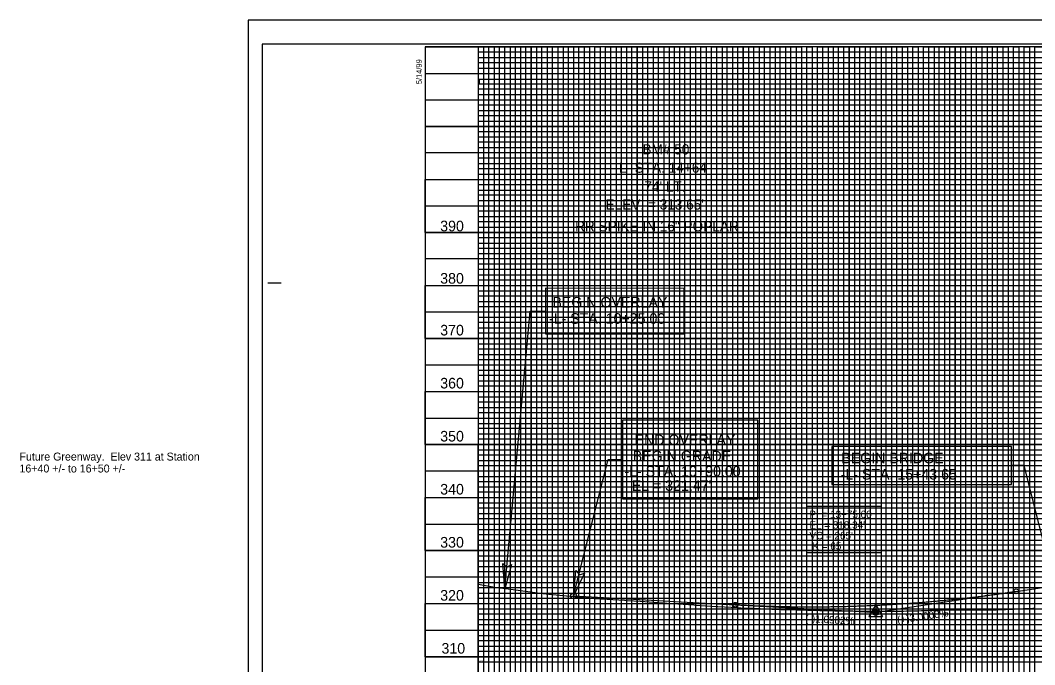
# Model space of a CAD drawing. Extents: x 574125 to 576234, y -56630 to -55530.
# Drawn here: x 574125 to 575082, y -56137 to -55530 of the extents above; entities that cross this region are included whole.
import ezdxf

# ---------------------------------------------------------------- set-up
doc = ezdxf.new("R2010")
doc.units = 0
for name, color, linetype in [('Default', 7, 'Continuous'), ('Exist Profile Cell', 7, 'Continuous'), ('Exist Vertical Profile Ground Line', 7, 'Continuous'), ('Exist Vertical Profile Vertical Axis Label', 7, 'Continuous'), ('Prop Grid Mask', 7, 'Continuous'), ('Prop PFL VPI Symbol CELL', 7, 'Continuous'), ('Prop Roadway Profile Bench Mark Info Text', 7, 'Continuous'), ('Prop Vertical Profile Curve Label', 7, 'Continuous'), ('Prop Vertical Profile Grade', 7, 'Continuous'), ('Prop Vertical Profile Grade Label', 7, 'Continuous'), ('Prop VPI Label', 7, 'Continuous'), ('Sheet DOT Grid CELL', 7, 'Continuous'), ('Sheet Plot Border Inside CELL', 7, 'Continuous'), ('Sheet Plot Border Outside CELL', 7, 'Continuous'), ('Sheet Profile CELL', 7, 'Continuous'), ('Sheet Profile Grid Major CELL', 7, 'Continuous'), ('Sheet Profile Grid Middle CELL', 7, 'Continuous'), ('Sheet Profile Grid Minor CELL', 7, 'Continuous'), ('Typical Terminator CELL', 7, 'Continuous')]:
    doc.layers.add(name, color=color, linetype=linetype)

msp = doc.modelspace()

# ---------------------------------------------------------------- linework, layer by layer
at = {"layer": 'Exist Profile Cell'}
msp.add_line((574556.81, -56179.85), (574556.81, -55929.85), dxfattribs=at)
at = {"layer": 'Exist Vertical Profile Ground Line'}
for points in [[(574556.81, -56061.37), (574572.39, -56064.2), (574584.89, -56065.93), (574585.5, -56066.03), (574614.78, -56070.08), (574615.19, -56070.12), (574626.34, -56071.21), (574627.11, -56071.28), (574656.54, -56074.14), (574667.14, -56074.83), (574667.54, -56074.87), (574694.84, -56076.65), (574697.37, -56076.82), (574709.71, -56077.66), (574739.43, -56079.69), (574740.03, -56079.73), (574760.22, -56081.05), (574761.44, -56081.13), (574781.02, -56082.41), (574782.8, -56082.51), (574801.58, -56083.57), (574804.41, -56083.71), (574814.2, -56084.14), (574817.02, -56084.26), (574819.84, -56084.38), (574822.04, -56084.48), (574822.66, -56084.5), (574825.48, -56084.6), (574826.57, -56084.64), (574828.31, -56084.7), (574831.13, -56084.8), (574833.95, -56084.9), (574836.77, -56085), (574839.59, -56085.1), (574842.57, -56085.21), (574845.23, -56085.27), (574848.12, -56085.35), (574850.87, -56085.43), (574853.69, -56085.51), (574856.51, -56085.59), (574859.33, -56085.67), (574862.15, -56085.75), (574863.21, -56085.78), (574864.98, -56085.82), (574867.8, -56085.89), (574869.54, -56085.93), (574870.62, -56085.96), (574873.44, -56086.02), (574876.26, -56086.09), (574879.08, -56086.16), (574881.9, -56086.23), (574885.01, -56086.3), (574887.54, -56086.36), (574890.36, -56086.42), (574891.83, -56086.45), (574893.18, -56086.47), (574896, -56086.52), (574898.82, -56086.57), (574901.65, -56086.62), (574904.47, -56086.67), (574906.83, -56086.71), (574907.29, -56086.72), (574910.11, -56086.77), (574912.93, -56086.82), (574914.84, -56086.86), (574915.75, -56086.86), (574918.57, -56086.88), (574921.39, -56086.91), (574924.21, -56086.93), (574927.03, -56086.95), (574929.85, -56086.97), (574931.16, -56086.98), (574932.67, -56086.99), (574935.5, -56087.01), (574938.32, -56087.02), (574939.48, -56087.03), (574941.14, -56087.02), (574943.96, -56087), (574946.78, -56086.99), (574949.6, -56086.97), (574952.42, -56086.95), (574955.49, -56086.93), (574958.06, -56086.85), (574960.88, -56086.76), (574962.45, -56086.72), (574963.7, -56086.69), (574966.52, -56086.62), (574969.34, -56086.55), (574972.17, -56086.48), (574974.99, -56086.42), (574975.77, -56086.4), (574977.81, -56086.32), (574980.63, -56086.22), (574982.77, -56086.13), (574983.45, -56086.12), (574986.27, -56086.04), (574989.09, -56085.97), (574991.91, -56085.89), (574994.73, -56085.82), (574996.06, -56085.79), (574997.55, -56085.77)], [(574997.55, -56085.77), (575000.37, -56085.75), (575003.19, -56085.73), (575003.75, -56085.72), (575006.01, -56085.72), (575008.84, -56085.71), (575011.66, -56085.7), (575014.48, -56085.69), (575017.3, -56085.69), (575017.86, -56085.69), (575020.12, -56085.67), (575022.94, -56085.66), (575025.21, -56085.65), (575025.76, -56085.65), (575028.58, -56085.65), (575031.4, -56085.65), (575034.22, -56085.65), (575037.04, -56085.66), (575039.86, -56085.66), (575042.68, -56085.61), (575044.32, -56085.58), (575045.51, -56085.55), (575048.33, -56085.47), (575051.15, -56085.39), (575054.15, -56085.31), (575056.79, -56085.18), (575059.61, -56085.05), (575062.43, -56084.91), (575065.25, -56084.78), (575068.07, -56084.65), (575070.89, -56084.51), (575072.07, -56084.46), (575073.71, -56084.42), (575076.53, -56084.35), (575079.35, -56084.29), (575080.4, -56084.26), (575082.18, -56084.18)]]:
    msp.add_lwpolyline(points, dxfattribs=at)
at = {"layer": 'Prop Grid Mask'}
for points in [[(574626.87, -55644.35), (574846.97, -55644.35), (574846.97, -55734.99), (574626.87, -55734.99)], [(574620.15, -55825.39), (574751.21, -55825.58), (574751.21, -55782.72), (574620.15, -55782.53)], [(574692.9, -55980.94), (574820.51, -55980.94), (574820.51, -55907), (574692.9, -55907)], [(575059.93, -55931.77), (574890.52, -55931.77), (574890.52, -55967.64), (575059.93, -55967.64)], [(574866.74, -55987.79), (574937.04, -55987.79), (574937.04, -56031.91), (574866.74, -56031.91)]]:
    msp.add_lwpolyline(points, close=True, dxfattribs=at)
at = {"layer": 'Prop PFL VPI Symbol CELL'}
for p, q in [((574931.76, -56080.8), (574925.31, -56092)), ((574931.76, -56080.8), (574938.26, -56092)), ((574925.31, -56092), (574938.26, -56092))]:
    msp.add_line(p, q, dxfattribs=at)
for radius in [1.75, 1.2]:
    msp.add_circle((574931.76, -56088.28), radius, dxfattribs=at)
at = {"layer": 'Prop Vertical Profile Curve Label'}
for centre in [(575064.31, -56068.27), (574799.31, -56080.87)]:
    msp.add_circle(centre, 2.25, dxfattribs=at)
at = {"layer": 'Prop Vertical Profile Grade'}
for p, q in [((575064.31, -56068.27), (575256.81, -56039.4)), ((574646.81, -56072.5), (574799.31, -56080.87))]:
    msp.add_line(p, q, dxfattribs=at)
msp.add_spline([(574799.31, -56080.87), (574804.61, -56081.15), (574809.91, -56081.41), (574815.21, -56081.65), (574820.51, -56081.86), (574825.81, -56082.05), (574831.11, -56082.23), (574836.41, -56082.38), (574841.71, -56082.5), (574847.01, -56082.61), (574852.31, -56082.7), (574857.61, -56082.76), (574862.91, -56082.8), (574868.21, -56082.82), (574873.51, -56082.82), (574878.81, -56082.79), (574884.11, -56082.75), (574889.41, -56082.68), (574894.71, -56082.59), (574900.01, -56082.48), (574905.31, -56082.35), (574910.61, -56082.19), (574915.91, -56082.02), (574921.21, -56081.82), (574926.51, -56081.6), (574931.81, -56081.36), (574937.11, -56081.1), (574942.41, -56080.81), (574947.71, -56080.51), (574953.01, -56080.18), (574958.31, -56079.83), (574963.61, -56079.46), (574968.91, -56079.06), (574974.21, -56078.65), (574979.51, -56078.21), (574984.81, -56077.75), (574990.11, -56077.27), (574995.41, -56076.77), (575000.71, -56076.25), (575006.01, -56075.7), (575011.31, -56075.14), (575016.61, -56074.55), (575021.91, -56073.94), (575027.21, -56073.31), (575032.51, -56072.65), (575037.81, -56071.98), (575043.11, -56071.28), (575048.41, -56070.56), (575053.71, -56069.82), (575059.01, -56069.06), (575064.31, -56068.27)], degree=3, dxfattribs=at)
at = {"layer": 'Prop VPI Label'}
for p, q in [((574581.81, -56065.91), (574605.91, -55803.96)), ((574605.91, -55803.96), (574620.15, -55803.96)), ((574646.81, -56072.5), (574679.38, -55943.97)), ((574679.38, -55943.97), (574692.9, -55943.97)), ((575071.74, -55949.7), (575059.93, -55949.7)), ((575100.46, -56062.85), (575071.74, -55949.7)), ((575064.31, -56068.27), (574934.53, -56087.74)), ((574799.31, -56080.87), (574929.06, -56088))]:
    msp.add_line(p, q, dxfattribs=at)
for centre in [(574646.81, -56072.5), (574931.81, -56088.15)]:
    msp.add_circle(centre, 2.75, dxfattribs=at)
at = {"layer": 'Sheet DOT Grid CELL'}
for p, q in [((574556.81, -55554.85), (574556.81, -56579.85)), ((574606.81, -55554.85), (574606.81, -56579.85)), ((574656.81, -55554.85), (574656.81, -56579.85)), ((574706.81, -55554.85), (574706.81, -56579.85)), ((574756.81, -55554.85), (574756.81, -56579.85)), ((574806.81, -55554.85), (574806.81, -56579.85)), ((574856.81, -55554.85), (574856.81, -56579.85)), ((574906.81, -55554.85), (574906.81, -56579.85)), ((574956.81, -55554.85), (574956.81, -56579.85)), ((575006.81, -55554.85), (575006.81, -56579.85)), ((575056.81, -55554.85), (575056.81, -56579.85)), ((574506.81, -55579.85), (575806.76, -55579.85)), ((574506.81, -55629.85), (575806.76, -55629.85)), ((574506.81, -55679.85), (575806.76, -55679.85)), ((574506.81, -55729.85), (576006.81, -55729.85)), ((574506.81, -55779.85), (576006.81, -55779.85)), ((574506.81, -55829.85), (576006.81, -55829.85)), ((574506.81, -55879.85), (576006.81, -55879.85)), ((574506.81, -55929.85), (576006.81, -55929.85)), ((574506.81, -55979.85), (576006.81, -55979.85)), ((574506.81, -56029.85), (576006.81, -56029.85)), ((574506.81, -56079.85), (576006.81, -56079.85)), ((574506.81, -56129.85), (576006.81, -56129.85))]:
    msp.add_line(p, q, dxfattribs=at)
at = {"layer": 'Sheet Plot Border Inside CELL'}
msp.add_lwpolyline([(576019.31, -55552.3), (574352.81, -55552.3), (574352.81, -56607.4), (576019.31, -56607.4)], close=True, dxfattribs=at)
at = {"layer": 'Sheet Plot Border Outside CELL'}
msp.add_lwpolyline([(576023.81, -55529.85), (574339.81, -55529.85), (574339.81, -56629.85), (576023.81, -56629.85)], close=True, dxfattribs=at)
at = {"layer": 'Sheet Profile CELL'}
for p, q in [((576023.81, -55529.85), (574339.81, -55529.85)), ((574339.81, -55529.85), (574339.81, -56629.85)), ((574358.31, -55777.35), (574370.81, -55777.35))]:
    msp.add_line(p, q, dxfattribs=at)
msp.add_lwpolyline([(576006.81, -55554.85), (574506.81, -55554.85), (574506.81, -56604.85), (576006.81, -56604.85)], close=True, dxfattribs=at)
at = {"layer": 'Sheet Profile Grid Major CELL'}
for points in [[(574506.81, -55554.85), (574556.81, -55554.85), (574556.81, -56579.85), (574606.81, -56579.85), (574606.81, -55554.85), (574656.81, -55554.85), (574656.81, -56579.85), (574706.81, -56579.85), (574706.81, -55554.85), (574756.81, -55554.85), (574756.81, -56579.85), (574806.81, -56579.85), (574806.81, -55554.85), (574856.81, -55554.85), (574856.81, -56579.85), (574906.81, -56579.85), (574906.81, -55554.85), (574956.81, -55554.85), (574956.81, -56579.85), (575006.81, -56579.85), (575006.81, -55554.85), (575056.81, -55554.85), (575056.81, -56579.85), (575106.81, -56579.85)], [(575806.76, -55629.85), (574506.91, -55629.85), (574506.91, -55579.9), (575806.76, -55579.9)], [(576006.81, -55729.85), (574506.81, -55729.85), (574506.81, -55679.85), (575806.76, -55679.85)], [(576006.81, -55829.85), (574506.81, -55829.85), (574506.81, -55779.85), (576006.81, -55779.85)], [(576006.81, -55929.85), (574506.81, -55929.85), (574506.81, -55879.85), (576006.81, -55879.85)], [(576006.81, -56029.85), (574506.81, -56029.85), (574506.81, -55979.85), (576006.81, -55979.85)], [(576006.81, -56129.85), (574506.81, -56129.85), (574506.81, -56079.85), (576006.81, -56079.85)]]:
    msp.add_lwpolyline(points, dxfattribs=at)
at = {"layer": 'Sheet Profile Grid Middle CELL'}
for points in [[(574581.81, -56579.85), (574581.81, -55554.85), (574631.81, -55554.85), (574631.81, -56579.85), (574681.81, -56579.85), (574681.81, -55554.85), (574731.81, -55554.85), (574731.81, -56579.85), (574781.81, -56579.85), (574781.81, -55554.85), (574831.81, -55554.85), (574831.81, -56579.85), (574881.81, -56579.85), (574881.81, -55554.85), (574931.81, -55554.85), (574931.81, -56579.85), (574981.81, -56579.85), (574981.81, -55554.85), (575031.81, -55554.85), (575031.81, -56579.85), (575081.81, -56579.85), (575081.81, -55554.85), (575131.81, -55554.85)], [(574506.81, -55604.85), (575806.76, -55604.85)], [(575806.76, -55654.85), (574506.81, -55654.85), (574506.81, -55704.9), (576006.81, -55704.9)], [(576006.81, -55754.85), (574506.81, -55754.85), (574506.81, -55804.85), (576006.81, -55804.85)], [(576006.81, -55854.85), (574506.81, -55854.85), (574506.81, -55904.85), (576006.81, -55904.85)], [(576006.81, -55954.85), (574506.81, -55954.85), (574506.81, -56004.85), (576006.81, -56004.85)], [(576006.81, -56054.85), (574506.81, -56054.85), (574506.81, -56104.85), (576006.81, -56104.85)]]:
    msp.add_lwpolyline(points, dxfattribs=at)
at = {"layer": 'Sheet Profile Grid Minor CELL'}
for p, q in [((575956.81, -55734.85), (574556.81, -55734.85)), ((574556.81, -55734.85), (574556.81, -55739.85)), ((574556.81, -55739.85), (575956.81, -55739.85)), ((575956.81, -55759.85), (574556.81, -55759.85))]:
    msp.add_line(p, q, dxfattribs=at)
for points in [[(574561.81, -55554.85), (574566.81, -55554.85), (574571.81, -55554.85), (574576.81, -55554.85), (574586.81, -55554.85), (574553.76, -55554.85), (574558.76, -55554.85), (574516.81, -55554.85), (574521.81, -55554.85), (574526.81, -55554.85), (574536.81, -55554.85), (574541.81, -55554.85), (574546.81, -55554.85), (574551.81, -55554.85), (574561.81, -55554.85), (574561.81, -56579.85)], [(574566.81, -56579.85), (574566.81, -55554.85), (574571.81, -55554.85), (574571.81, -56579.85)], [(574576.81, -56579.85), (574576.81, -55554.85), (574586.81, -55554.85), (574586.81, -56579.85)], [(574591.81, -56579.85), (574591.81, -55554.85), (574596.81, -55554.85), (574596.81, -56579.85)], [(574601.81, -56579.85), (574601.81, -55554.85), (574611.81, -55554.85), (574611.81, -56579.85)], [(574616.81, -56579.85), (574616.81, -55554.85), (574621.81, -55554.85), (574621.81, -56579.85)], [(574626.81, -56579.85), (574626.81, -55554.85), (574636.81, -55554.85), (574636.81, -56579.85)], [(574641.81, -56579.85), (574641.81, -55554.85), (574646.81, -55554.85), (574646.81, -56579.85)], [(574651.81, -56579.85), (574651.81, -55554.85), (574661.81, -55554.85), (574661.81, -56579.85)], [(574666.81, -56579.85), (574666.81, -55554.85), (574671.81, -55554.85), (574671.81, -56579.85)], [(574676.81, -56579.85), (574676.81, -55554.85), (574686.81, -55554.85), (574686.81, -56579.85)], [(574691.81, -56579.85), (574691.81, -55554.85), (574696.81, -55554.85), (574696.81, -56579.85)], [(574701.81, -56579.85), (574701.81, -55554.85), (574711.81, -55554.85), (574711.81, -56579.85)], [(574716.81, -56579.85), (574716.81, -55554.85), (574721.81, -55554.85), (574721.81, -56579.85)], [(574726.81, -56579.85), (574726.81, -55554.85), (574736.81, -55554.85), (574736.81, -56579.85)], [(574741.81, -56579.85), (574741.81, -55554.85), (574746.81, -55554.85), (574746.81, -56579.85)], [(574751.81, -56579.85), (574751.81, -55554.85), (574761.81, -55554.85), (574761.81, -56579.85)], [(574766.81, -56579.85), (574766.81, -55554.85), (574766.81, -55554.85), (574771.81, -55554.85), (574771.81, -56579.85)], [(574776.81, -56579.85), (574776.81, -55554.85), (574786.81, -55554.85), (574786.81, -56579.85)], [(574791.81, -56579.85), (574791.81, -55554.85), (574796.81, -55554.85), (574796.81, -56579.85)], [(574801.81, -56579.85), (574801.81, -55554.85), (574811.81, -55554.85), (574811.81, -56579.85)], [(574816.81, -56579.85), (574816.81, -55554.85), (574821.81, -55554.85), (574821.81, -56579.85)], [(574826.81, -56579.85), (574826.81, -55554.85), (574836.81, -55554.85), (574836.81, -56579.85)], [(574841.81, -56579.85), (574841.81, -55554.85), (574846.81, -55554.85), (574846.81, -56579.85)], [(574851.81, -56579.85), (574851.81, -55554.85), (574861.81, -55554.85), (574861.81, -56579.85)], [(574866.81, -56579.85), (574866.81, -55554.85), (574871.81, -55554.85), (574871.81, -56579.85)], [(574876.81, -56579.85), (574876.81, -55554.85), (574886.81, -55554.85), (574886.81, -56579.85)], [(574891.81, -55554.85), (574891.81, -56579.85), (574896.81, -56579.85), (574896.81, -55554.85)], [(574891.81, -55555.45), (574891.81, -56579.85), (574896.81, -56579.85), (574896.81, -55555.45)], [(574901.81, -56579.85), (574901.81, -55554.85), (574911.81, -55554.85), (574911.81, -56579.85)], [(574916.81, -56579.85), (574916.81, -55554.85), (574921.81, -55554.85), (574921.81, -56579.85)], [(574926.81, -56579.85), (574926.81, -55554.85), (574936.81, -55554.85), (574936.81, -56579.85)], [(574941.81, -56579.85), (574941.81, -55554.85), (574946.81, -55554.85), (574946.81, -56579.85)], [(574951.81, -56579.85), (574951.81, -55554.85), (574961.81, -55554.85), (574961.81, -56579.85)], [(574966.81, -56579.85), (574966.81, -55554.85), (574971.81, -55554.85), (574971.81, -56579.85)], [(574976.81, -56579.85), (574976.81, -55554.85), (574986.81, -55554.85), (574986.81, -56579.85)], [(574991.81, -56579.85), (574991.81, -55554.85), (574996.81, -55554.85), (574996.81, -56579.85)], [(575001.81, -56579.85), (575001.81, -55554.85), (575011.81, -55554.85), (575011.81, -56579.85)], [(575016.81, -56579.85), (575016.81, -55554.85), (575021.81, -55554.85), (575021.81, -56579.85)], [(575026.81, -56579.85), (575026.81, -55554.85), (575036.81, -55554.85), (575036.81, -56579.85)], [(575041.81, -55554.85), (575041.81, -56579.85), (575046.81, -56579.85), (575046.81, -55554.85), (575051.81, -55554.85), (575051.81, -56579.85), (575061.81, -56579.85), (575061.81, -55554.85), (575066.81, -55554.85), (575066.81, -56579.85), (575071.81, -56579.85), (575071.81, -55554.85), (575076.81, -55554.85), (575076.81, -56579.85)], [(575806.76, -55559.85), (574556.81, -55559.85), (574556.81, -55564.85), (575806.76, -55564.85)], [(575806.76, -55569.85), (574556.81, -55569.85), (574556.81, -55574.85), (575806.76, -55574.85)], [(575806.76, -55585.6), (574557.81, -55585.6), (574557.81, -55589.85), (575806.76, -55589.85)], [(575806.76, -55594.85), (574556.81, -55594.85), (574556.81, -55599.85), (575806.76, -55599.85)], [(575806.76, -55609.85), (574556.81, -55609.85), (574556.81, -55614.85), (575806.76, -55614.85)], [(575806.76, -55619.85), (574556.81, -55619.85), (574556.81, -55624.85), (575806.76, -55624.85)], [(575806.76, -55634.85), (574556.81, -55634.85), (574556.81, -55639.85), (575806.76, -55639.85)], [(575806.76, -55644.85), (574556.81, -55644.85), (574556.81, -55649.85), (575806.76, -55649.85)], [(575806.76, -55659.85), (574556.81, -55659.85), (574556.81, -55664.85), (575806.76, -55664.85)], [(575806.76, -55669.85), (574556.81, -55669.85), (574556.81, -55674.85), (575806.76, -55674.85)], [(575806.76, -55684.85), (574556.81, -55684.85), (574556.81, -55689.85), (575806.76, -55689.85)], [(575956.81, -55694.85), (574556.81, -55694.85), (574556.81, -55694.85), (574556.81, -55714.85), (575956.81, -55714.85)], [(574556.81, -55699.85), (575956.81, -55699.85)], [(575956.81, -55709.85), (574556.81, -55709.85)], [(575956.81, -55719.85), (574556.81, -55719.85), (574556.81, -55724.85), (575956.81, -55724.85)], [(575956.81, -55744.85), (574556.81, -55744.85), (574556.81, -55749.85), (575956.81, -55749.85)], [(575956.81, -55764.85), (574556.81, -55764.85), (574556.81, -55769.85), (575956.81, -55769.85)], [(575956.81, -55774.85), (574556.81, -55774.85)], [(574556.81, -55784.85), (575956.81, -55784.85)], [(575956.81, -55789.85), (574556.81, -55789.85), (574556.81, -55794.85), (575956.81, -55794.85)], [(575956.81, -55799.85), (574556.81, -55799.85), (574556.81, -55809.85), (575956.81, -55809.85)], [(575956.81, -55814.85), (574556.81, -55814.85), (574556.81, -55819.85), (575956.81, -55819.85)], [(575956.81, -55824.85), (574556.81, -55824.85), (574556.81, -55834.85), (575956.81, -55834.85)], [(575956.81, -55839.85), (574556.81, -55839.85), (574556.81, -55844.85), (575956.81, -55844.85)], [(575956.81, -55849.85), (574556.81, -55849.85), (574556.81, -55859.85), (575956.81, -55859.85)], [(575956.81, -55864.85), (574556.81, -55864.85), (574556.81, -55869.85), (575956.81, -55869.85)], [(575956.81, -55874.85), (574556.81, -55874.85), (574556.81, -55884.85), (575956.81, -55884.85)], [(575956.81, -55889.85), (574556.81, -55889.85), (574556.81, -55894.85), (575956.81, -55894.85)], [(575956.81, -55899.85), (574556.81, -55899.85), (574556.81, -55909.85), (575956.81, -55909.85)], [(575956.81, -55914.85), (574556.81, -55914.85), (574556.81, -55919.85), (575956.81, -55919.85)], [(575956.81, -55924.85), (574556.81, -55924.85), (574556.81, -55934.85), (575956.81, -55934.85)], [(575956.81, -55939.85), (574556.81, -55939.85), (574556.81, -55944.85), (575956.81, -55944.85)], [(575956.81, -55949.85), (574556.81, -55949.85), (574556.81, -55959.85), (575956.81, -55959.85)], [(575956.81, -55964.85), (574556.81, -55964.85), (574556.81, -55969.85), (575956.81, -55969.85)], [(575956.81, -55974.85), (574556.81, -55974.85), (574556.81, -55984.85), (575956.81, -55984.85)], [(575956.81, -55989.85), (574556.81, -55989.85), (574556.81, -55994.85), (575956.81, -55994.85)], [(575956.81, -55999.85), (574556.81, -55999.85), (574556.81, -56009.85), (575956.81, -56009.85)], [(575956.81, -56014.85), (574556.81, -56014.85), (574556.81, -56019.85), (575956.81, -56019.85)], [(575956.81, -56024.85), (574556.81, -56024.85), (574556.81, -56034.85), (575956.81, -56034.85)], [(575956.81, -56039.85), (574556.81, -56039.85), (574556.81, -56044.85), (575956.81, -56044.85)], [(575956.81, -56049.85), (574556.81, -56049.85), (574556.81, -56059.85), (575956.81, -56059.85)], [(575956.81, -56064.85), (574556.81, -56064.85), (574556.81, -56069.85), (575956.81, -56069.85)], [(575956.81, -56074.85), (574556.81, -56074.85)], [(574556.81, -56084.85), (575956.81, -56084.85)], [(575956.81, -56089.85), (574556.81, -56089.85), (574556.81, -56094.85), (575956.81, -56094.85)], [(575956.81, -56099.85), (574556.81, -56099.85), (574556.81, -56109.85), (575956.81, -56109.85)], [(575956.81, -56114.85), (574556.81, -56114.85), (574556.81, -56119.85), (575956.81, -56119.85)], [(575956.81, -56124.85), (574556.81, -56124.85), (574556.81, -56134.85), (575956.81, -56134.85)]]:
    msp.add_lwpolyline(points, dxfattribs=at)
at = {"layer": 'Typical Terminator CELL'}
for points in [[(574588.09, -56043.05), (574581.8, -56065.98), (574579.94, -56042.12), (574583.79, -56045.51)], [(574656.91, -56050.97), (574646.81, -56072.5), (574649.03, -56048.67), (574652.26, -56052.66)]]:
    msp.add_lwpolyline(points, close=True, dxfattribs=at)

# ---------------------------------------------------------------- texts
at = {"layer": 'Default'}
for s, p in [('Future Greenway.  Elev 311 at Station ', (574123.99, -55944.93)), ('16+40 +/- to 16+50 +/-', (574123.99, -55956.18))]:
    msp.add_text(s, height=7.5, dxfattribs=at).set_placement(p)
at = {"layer": 'Exist Profile Cell'}
msp.add_text('RDY', height=2, dxfattribs=at).set_placement((574556.81, -56135.22))
at = {"layer": 'Exist Vertical Profile Vertical Axis Label'}
for s, p in [('390', (574520.93, -55728.8)), ('380', (574520.93, -55778.14)), ('370', (574520.93, -55826.98)), ('360', (574520.93, -55876.98)), ('350', (574520.93, -55926.98)), ('340', (574520.93, -55976.98)), ('330', (574520.93, -56026.98)), ('320', (574520.93, -56076.98)), ('310', (574522.13, -56126.98))]:
    msp.add_text(s, height=10, rotation=360, dxfattribs=at).set_placement(p)
at = {"layer": 'Prop Roadway Profile Bench Mark Info Text'}
for s, p in [('BM# 50 ', (574711.75, -55656.32)), ("74' LT.", (574713.53, -55691.28)), (" ELEV. = 313.65'", (574673.39, -55708.27)), (' RR SPIKE IN 16" POPLAR ', (574644.6, -55728.83))]:
    msp.add_text(s, height=9.6, rotation=0.00002, dxfattribs=at).set_placement(p)
msp.add_text('-L- STA. 14+64', height=9.6, dxfattribs=at).set_placement((574685.16, -55673.59))
at = {"layer": 'Prop Vertical Profile Curve Label'}
for s, p in [("VC = 265'", (574869.2, -56019.19)), ('K = 65', (574872.04, -56029.02))]:
    msp.add_text(s, height=7, dxfattribs=at).set_placement(p)
at = {"layer": 'Prop Vertical Profile Grade Label'}
for s, rotation, p in [('(-)1.0982%', 356.85691, (574865.25, -56097.11)), ('(+)3.0000%', 8.53077, (574952.63, -56098.93))]:
    msp.add_text(s, height=7, rotation=rotation, dxfattribs=at).set_placement(p)
at = {"layer": 'Prop VPI Label'}
for s, p in [('BEGIN OVERLAY', (574626.79, -55800.7)), ('-L- STA. 10+25.00', (574623.57, -55816)), ('END OVERLAY', (574704.31, -55930.39)), ('BEGIN GRADE', (574702.6, -55945.65)), ('BEGIN BRIDGE', (574899.36, -55947.54)), ('-L- STA. 10+90.00', (574694.71, -55960.05)), ('-L- STA. 15+43.65', (574898.72, -55962.85)), ("EL = 321.47'", (574701.65, -55973.51))]:
    msp.add_text(s, height=10, rotation=360, dxfattribs=at).set_placement(p)
for s, p in [('PI = 13+75.00', (574869.2, -55999.19)), ("EL = 318.34'", (574869.2, -56009.19))]:
    msp.add_text(s, height=7, dxfattribs=at).set_placement(p)
at = {"layer": 'Sheet Profile CELL'}
msp.add_text('5/14/99', height=5.25, rotation=90, dxfattribs=at).set_placement((574503.56, -55590.05))

doc.saveas('drawing.dxf')
